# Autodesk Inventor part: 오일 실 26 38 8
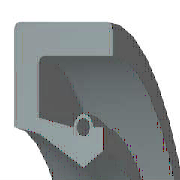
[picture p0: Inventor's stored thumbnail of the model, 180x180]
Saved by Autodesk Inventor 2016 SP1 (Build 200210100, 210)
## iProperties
IsCustomPart: 1
Created: 2012-02
Part Number: 오일 실 26 38 8
Material: 고무
Description: 오일-실
Document SubType Name: Modeling
Standard: KS B 2804
Designer: mduedu
Standards Organization: KS
Language: ko-KR
Size Designation: S - 26 38 8
Categories: <MemberInstance><Categories><Category DisplayName="샤프트 부품" InternalName="7f7aeb1f-a693-4053-b835-cee3144e0d98" Mnemonic="SHFT"><Category DisplayName="실링" Intern
Density: 0.93 g/cm^3
Appearance: 고무 - 검은색 - 버전 1.1
Author: mduedu
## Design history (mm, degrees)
revolve "본체" stored, may be unused: angle "d17" = 90 deg
revolve "스프링1" stored, may be unused: angle "d18" = 90 deg
body "Solid1"
sketch "스케치1"
  geometry: L1 (0, 19)-(8, 19); L2 (8, 19)-(8, 17.75); L3 (8, 17.75)-(1.75, 17.75); L4 (0, 19)-(0, 15.1); L5 (0, 15.1)-(1.75, 14.75); L6 (1.75, 14.75)-(4.9, 13); L7 (4.9, 13)-(0, 13); L8 (6.3, 13.875)-(6.3, 15.1); L9 (0, 0)-(9.586, 0) reference; L10 (4.9, 13)-(6.3, 13.875); L11 (0, 18)-(0, -3) reference; L12 (-1.917, 0)-(11.503, 0) reference; L13 (4.2, 15.1)-(1.75, 15.59); L14 (1.75, 15.59)-(1.75, 17.75); L15 (6.3, 15.1)-(5.6, 15.1); C1 r 0.455 at (4.9, 15.1); A1 r 0.7 centre (4.9, 15.1) between (5.6, 15.1) and (4.2, 15.1)
  constraints: 26 end point, 5 horizontal alignment, 4 perpendicular, 2 centre point, 2 collinear, 2 horizontal, 2 parallel, 2 point on circle, 2 point on line, 2 vertical alignment, 1 coincident
  dimensions: "d0" = 38 diameter of L1 L9 (= SD2); "d1" = 27.75 diameter of L8.start L9 (= ABDM); "d2" = 1.25 distance of L1.end L2.end (computed from SD); "d3" = 0.91 diameter of C1 (= SPDI); "d4" = 1.4 diameter of A1 (= SPDA); "d5" = 26 diameter of L6.end L9 (= NND); "d6" = 29.5 diameter of L5.end L9 (= TKDM); "d7" = 30.2 diameter of L4.end L9 (= HLDM); "d8" = 4.9 distance from line of C1.centre L4 (= SPDST); "d9" = 6.3 distance between parallel lines of L8 L4 (= SDI); "d10" = 8 distance between parallel lines of L2 L4 (= SWDT); "d12" = 1.75 distance between parallel lines of L14 L4 (= SD)
fillet "모깎기1" dims "d11" = 0.3 (= RR)
other parameters: "SD2" = 38 [user parameter; used in 1 equation term], "SWDT" = 8 [user parameter; used in 1 equation term], "RR" = 0.3 [user parameter; used in 1 equation term], "SD" = 1.75 [user parameter; used in 2 equation terms], "NND" = 26 [user parameter; used in 1 equation term], "SPDA" = 1.4 [user parameter; used in 1 equation term], "SPDI" = 0.91 [user parameter; used in 1 equation term], "TKDM" = 29.5 [user parameter; used in 1 equation term], "HLDM" = 30.2 [user parameter; used in 1 equation term], "ABDM" = 27.75 [user parameter; used in 1 equation term], "SDI" = 6.3 [user parameter; used in 1 equation term], "SPDST" = 4.9 [user parameter; used in 1 equation term], "d13" = 0, "d14" = 0, "d15" = 0, "LAB" = 0.35 [user parameter]
